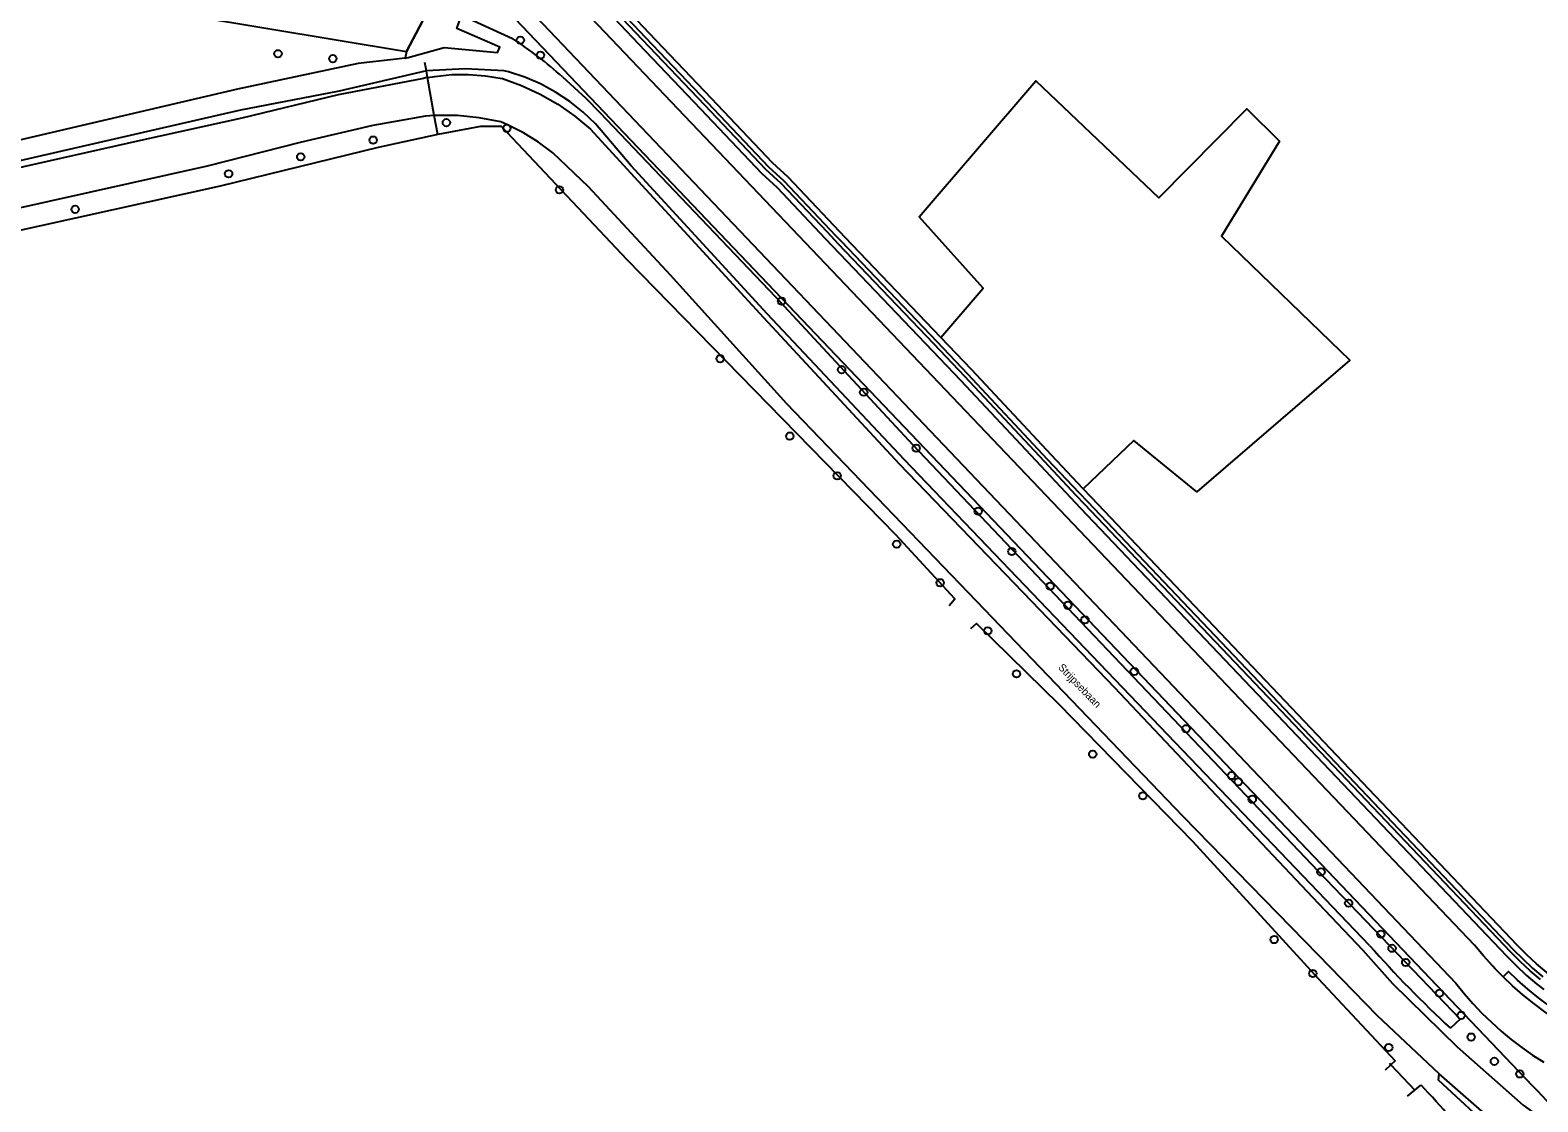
# Model space of a CAD drawing. Extents: x 152881 to 155736, y 382924 to 386919.
# Drawn here: x 153829.4 to 154029.1, y 383183.7 to 383325.6 of the extents above; entities that cross this region are included whole.
import ezdxf

# ---------------------------------------------------------------- set-up
doc = ezdxf.new("R2010")
doc.units = 0
for name, color, linetype in [('IMGEO_Boom', 7, 'Continuous'), ('IMGEO_Duiker', 7, 'Continuous'), ('IMGEO_Gemengd_bos', 7, 'Continuous'), ('IMGEO_Groenvoorziening', 7, 'Continuous'), ('IMGEO_Hek', 7, 'Continuous'), ('IMGEO_Loofbos', 7, 'Continuous'), ('IMGEO_Openbare_ruimte_label', 7, 'Continuous'), ('IMGEO_Rijbaan_lokaal_gesloten', 7, 'Continuous'), ('IMGEO_Rijbaan_lokaal_halfverhard', 7, 'Continuous'), ('IMGEO_Sloot', 7, 'Continuous'), ('IMGEO_Waterloop', 7, 'Continuous')]:
    doc.layers.add(name, color=color, linetype=linetype)

msp = doc.modelspace()

# ---------------------------------------------------------------- linework, layer by layer
at = {"layer": 'IMGEO_Boom'}
for centre in [(153894.33, 383324.27), (153862.24, 383322.48), (153896.99, 383322.3), (153869.49, 383321.83), (153884.54, 383313.35), (153892.54, 383312.61), (153874.84, 383311.05), (153865.25, 383308.83), (153855.7, 383306.59), (153899.51, 383304.45), (153835.39, 383301.88), (153928.93, 383289.72), (153920.79, 383282.1), (153936.88, 383280.65), (153939.8, 383277.66), (153930.01, 383271.86), (153946.76, 383270.25), (153936.3, 383266.59), (153954.96, 383261.91), (153944.17, 383257.55), (153959.42, 383256.58), (153949.92, 383252.44), (153964.49, 383251.99), (153966.83, 383249.45), (153969.1, 383247.53), (153956.23, 383246.08), (153960.03, 383240.37), (153975.64, 383240.7), (153982.49, 383233.11), (153970.13, 383229.75), (153988.5, 383226.9), (153989.41, 383226.09), (153976.77, 383224.22), (153991.26, 383223.77), (154000.36, 383214.15), (154004.02, 383210.02), (153994.17, 383205.19), (154008.28, 383205.9), (154009.77, 383204.04), (153999.28, 383200.71), (154011.58, 383202.17), (154016.05, 383198.11), (154018.91, 383195.16), (154009.33, 383190.9), (154020.24, 383192.29), (154023.32, 383189.07), (154026.69, 383187.4)]:
    msp.add_circle(centre, 0.489, dxfattribs=at)
at = {"layer": 'IMGEO_Duiker'}
for points in [[(153883.39, 383311.77), (153882.94, 383314.3), (153882.05, 383319.32), (153881.89, 383320.23), (153881.7, 383321.3)], [(154009.42, 383188.81), (154009.62, 383188.6), (154012.79, 383185.27)]]:
    msp.add_lwpolyline(points, dxfattribs=at)
at = {"layer": 'IMGEO_Gemengd_bos'}
for points in [[(153631.89, 383257.44), (153692.52, 383353.78), (153729.12, 383347.72), (153879.25, 383322.78)], [(153879.25, 383322.78), (153879.1, 383321.89)]]:
    msp.add_lwpolyline(points, dxfattribs=at)
at = {"layer": 'IMGEO_Groenvoorziening'}
for points in [[(153900.28, 383334.06), (153909.98, 383323.79), (153918.2, 383315.18), (153926.29, 383306.65), (153928.33, 383304.77), (153934.71, 383298.03), (153952.67, 383279.23), (153963.21, 383267.96), (153968.51, 383262.33), (154024.92, 383203.04), (154026.21, 383201.75), (154027.55, 383200.5), (154028.94, 383199.31), (154029.85, 383198.59)], [(153882.71, 383329.32), (153879.25, 383322.78)], [(154296.01, 383110.08), (154286.6, 383112.34), (154034.03, 383179.91), (154030.33, 383183.78), (154029.6, 383184.55), (154029.12, 383185.06), (154028.39, 383185.82), (153891.83, 383329), (153882.74, 383329.15), (153882.71, 383329.32)], [(153968.87, 383264.87), (153964.66, 383269.33), (153954.12, 383280.62), (153950.02, 383284.91)], [(154054.27, 383186.13), (154054.52, 383187.09), (154045.15, 383189.58), (154043.42, 383190.08), (154041.71, 383190.65), (154040.03, 383191.28), (154038.38, 383191.98), (154036.75, 383192.74), (154035.16, 383193.57), (154033.6, 383194.46), (154032.07, 383195.42), (154030.59, 383196.43), (154029.15, 383197.5), (154027.75, 383198.63), (154026.4, 383199.82), (154025.18, 383200.97), (154024.49, 383200.24)]]:
    msp.add_lwpolyline(points, dxfattribs=at)
at = {"layer": 'IMGEO_Hek'}
for points in [[(153469.72, 383000.07), (153586.51, 383185.61), (153598.23, 383208.99), (153609.84, 383223.7), (153623.81, 383244.6), (153692.52, 383353.78), (153729.12, 383347.72), (153879.25, 383322.78), (153882.71, 383329.32)], [(153882.74, 383329.15), (153891.83, 383329), (154028.39, 383185.82)], [(154028.39, 383185.82), (154029.12, 383185.06)]]:
    msp.add_lwpolyline(points, dxfattribs=at)
at = {"layer": 'IMGEO_Loofbos'}
for points in [[(153950.02, 383284.91), (153937.34, 383298.17), (153935.89, 383299.69), (153929.79, 383306.15), (153927.74, 383308.03), (153919.66, 383316.55), (153911.44, 383325.16), (153901.73, 383335.43), (153900.43, 383336.87), (153899.18, 383338.35), (153897.98, 383339.88), (153896.85, 383341.45), (153895.78, 383343.07), (153894.77, 383344.73), (153893.82, 383346.42), (153892.94, 383348.15), (153892.12, 383349.91), (153891.37, 383351.69), (153890.69, 383353.51), (153890.08, 383355.35), (153889.54, 383357.21), (153889.07, 383359.1), (153888.67, 383360.99), (153886.97, 383369.95)], [(153950.02, 383284.91), (153955.61, 383291.44), (153947.13, 383300.88), (153962.6, 383318.87), (153978.89, 383303.41), (153990.56, 383315.18), (153994.85, 383310.89), (153987.18, 383298.34), (154004.2, 383281.92), (153983.93, 383264.48), (153975.58, 383271.26), (153968.87, 383264.87)], [(154043.82, 383192.63), (154040.1, 383194.22), (154034.45, 383197.79), (154032.99, 383198.75), (154031.58, 383199.78), (154030.21, 383200.86), (154028.88, 383201.99), (154027.6, 383203.18), (154026.37, 383204.42), (153969.96, 383263.71), (153968.87, 383264.87)]]:
    msp.add_lwpolyline(points, dxfattribs=at)
at = {"layer": 'IMGEO_Rijbaan_lokaal_gesloten'}
for points in [[(154024.49, 383200.24), (154024.39, 383200.34), (154023.43, 383201.34), (154023.11, 383201.66), (154021.89, 383203.02), (154020.71, 383204.44), (153898.42, 383332.86)], [(153892.95, 383331.06), (154018.23, 383199.42), (154019.32, 383198.05), (154020.46, 383196.73), (154021.67, 383195.47), (154022.92, 383194.25), (154024.22, 383193.08), (154025.56, 383191.97), (154026.96, 383190.91), (154028.39, 383189.91), (154029.86, 383188.98)], [(154054.27, 383186.13), (154044.89, 383188.62), (154043.12, 383189.13), (154041.38, 383189.7), (154039.66, 383190.35), (154037.97, 383191.06), (154036.31, 383191.85), (154034.68, 383192.69), (154033.08, 383193.6), (154031.53, 383194.58), (154030.01, 383195.62), (154028.54, 383196.71), (154027.11, 383197.87), (154025.73, 383199.08), (154024.49, 383200.24)]]:
    msp.add_lwpolyline(points, dxfattribs=at)
at = {"layer": 'IMGEO_Rijbaan_lokaal_halfverhard'}
for points in [[(153882.05, 383319.32), (153881.77, 383319.27), (153881.49, 383319.21), (153870.23, 383317.05), (153857.47, 383313.95), (153844.02, 383310.97), (153781.6, 383296.94), (153754.73, 383291.13), (153729.71, 383285.1), (153677.51, 383272.68), (153671.82, 383271.14)], [(153882.05, 383319.32), (153883.02, 383319.48), (153885.24, 383319.71), (153887.48, 383319.74), (153889.7, 383319.57), (153891.91, 383319.19), (153891.95, 383319.18), (153894.5, 383318.27), (153896.96, 383317.14), (153899.32, 383315.79), (153901.54, 383314.23), (153903.61, 383312.49), (153908.43, 383307.22), (153926.54, 383287.57), (153944.5, 383268.19), (153962.01, 383250), (153973.03, 383238.56), (154000, 383210), (154005.89, 383203.77), (154009.85, 383199.39), (154018.39, 383191.01), (154027.14, 383183.27), (154031.63, 383179.99)], [(153882.94, 383314.3), (153882.05, 383319.32)], [(153882.94, 383314.3), (153881.79, 383314.23), (153874.8, 383312.97), (153865.19, 383310.72), (153852.87, 383307.59), (153733.15, 383280.88), (153707.05, 383275.08), (153678.39, 383268.03)], [(154015.99, 383187.44), (154007.84, 383195.08), (154000, 383203.18), (153982.11, 383221.49), (153954.73, 383250), (153929.63, 383276.14), (153914.2, 383293.17), (153903.34, 383304.86), (153898.63, 383309.35), (153896.75, 383310.76), (153894.75, 383312.01), (153892.65, 383313.07), (153891.75, 383313.45), (153888.9, 383313.99), (153886.02, 383314.28), (153883.13, 383314.3), (153882.94, 383314.3)], [(154032.13, 383165.8), (154031.68, 383166.72), (154030.54, 383169.34), (154025.99, 383176.29), (154023.57, 383179.52), (154015.93, 383186.56), (154015.99, 383187.44)], [(154049.17, 383165.75), (154045.2, 383167.4), (154035.94, 383172.13), (154030.85, 383175.27), (154024.47, 383179.99), (154015.99, 383187.44)]]:
    msp.add_lwpolyline(points, dxfattribs=at)
at = {"layer": 'IMGEO_Sloot'}
msp.add_lwpolyline([(154011.81, 383184.46), (154012.79, 383185.27), (154013.6, 383185.92)], dxfattribs=at)
msp.add_arc((153949.96, 383124.85), 88.21, 36.2056, 43.8165, dxfattribs=at)
at = {"layer": 'IMGEO_Waterloop'}
for points in [[(153901.18, 383334.92), (153910.89, 383324.65), (153919.12, 383316.03), (153927.19, 383307.52), (153929.24, 383305.64), (153935.35, 383299.18), (153935.54, 383298.98), (153935.94, 383298.55), (153936.8, 383297.65), (153949.47, 383284.39), (153953.57, 383280.11), (153964.11, 383268.82), (153968.33, 383264.35), (153969.42, 383263.19), (154025.83, 383203.9), (154027.08, 383202.64), (154028.38, 383201.43), (154029.73, 383200.28)], [(154029.41, 383199.89), (154028.05, 383201.06), (154026.73, 383202.29), (154025.47, 383203.55), (153969.06, 383262.85), (153967.96, 383264.01), (153963.75, 383268.47), (153953.21, 383279.76), (153949.11, 383284.05), (153936.43, 383297.31), (153934.99, 383298.84), (153928.89, 383305.29), (153926.84, 383307.16), (153918.76, 383315.69), (153910.53, 383324.3), (153900.82, 383334.58)], [(153879.1, 383321.89), (153879.46, 383321.99), (153884.26, 383323.32), (153891.31, 383322.64), (153891.6, 383323.36), (153885.94, 383325.81), (153886.55, 383327.57), (153893.3, 383324.48)], [(153879.1, 383321.89), (153879.1, 383321.89), (153872.87, 383321.17), (153856.86, 383317.78), (153731.18, 383288.41), (153694.24, 383279.54)], [(154006.79, 383204.41), (154000, 383211.51), (153963.14, 383250), (153945.22, 383268.71), (153927.04, 383288.03), (153909.03, 383307.64), (153904.28, 383313.18), (153902.65, 383314.74), (153900.88, 383316.16), (153898.99, 383317.4), (153897, 383318.48), (153894.92, 383319.37), (153892.77, 383320.07), (153892.17, 383320.23), (153887.01, 383320.46), (153881.89, 383320.23), (153870.36, 383317.54), (153857.26, 383315.01), (153694.93, 383277.76), (153694.24, 383279.54)], [(153899.93, 383319.42), (153903.02, 383316.61), (153904.84, 383314.7), (153928.13, 383290.29), (153946.29, 383270.68), (153965.97, 383250), (154000, 383214.23), (154018.8, 383194.64), (154017.52, 383193.45)], [(153951.1, 383249.43), (153951.89, 383250.32), (153944.04, 383258.78), (153908.47, 383295.19), (153891.86, 383312.86), (153889.07, 383312.85), (153883.39, 383311.77), (153875.51, 383310.08), (153854.57, 383304.93), (153735.39, 383278.59), (153710.59, 383272.44), (153679.58, 383265.48)], [(153954.01, 383246.38), (153954.72, 383247.04), (153965.68, 383236.31), (153983.35, 383218.24), (154000, 383200.02), (154010.17, 383189.12), (154009.62, 383188.6), (154008.85, 383187.9)]]:
    msp.add_lwpolyline(points, dxfattribs=at)
for centre, radius, start, end in [((153865.83, 383281.67), 50.86, 47.9083, 57.3131), ((154120.84, 383305.3), 152.27, 221.4967, 227.2729)]:
    msp.add_arc(centre, radius, start, end, dxfattribs=at)

# ---------------------------------------------------------------- texts
at = {"layer": 'IMGEO_Openbare_ruimte_label'}
msp.add_text('Strijpsebaan', height=1, rotation=313.8656, dxfattribs=at).set_placement((153965.48, 383241.15))

doc.saveas('drawing.dxf')
